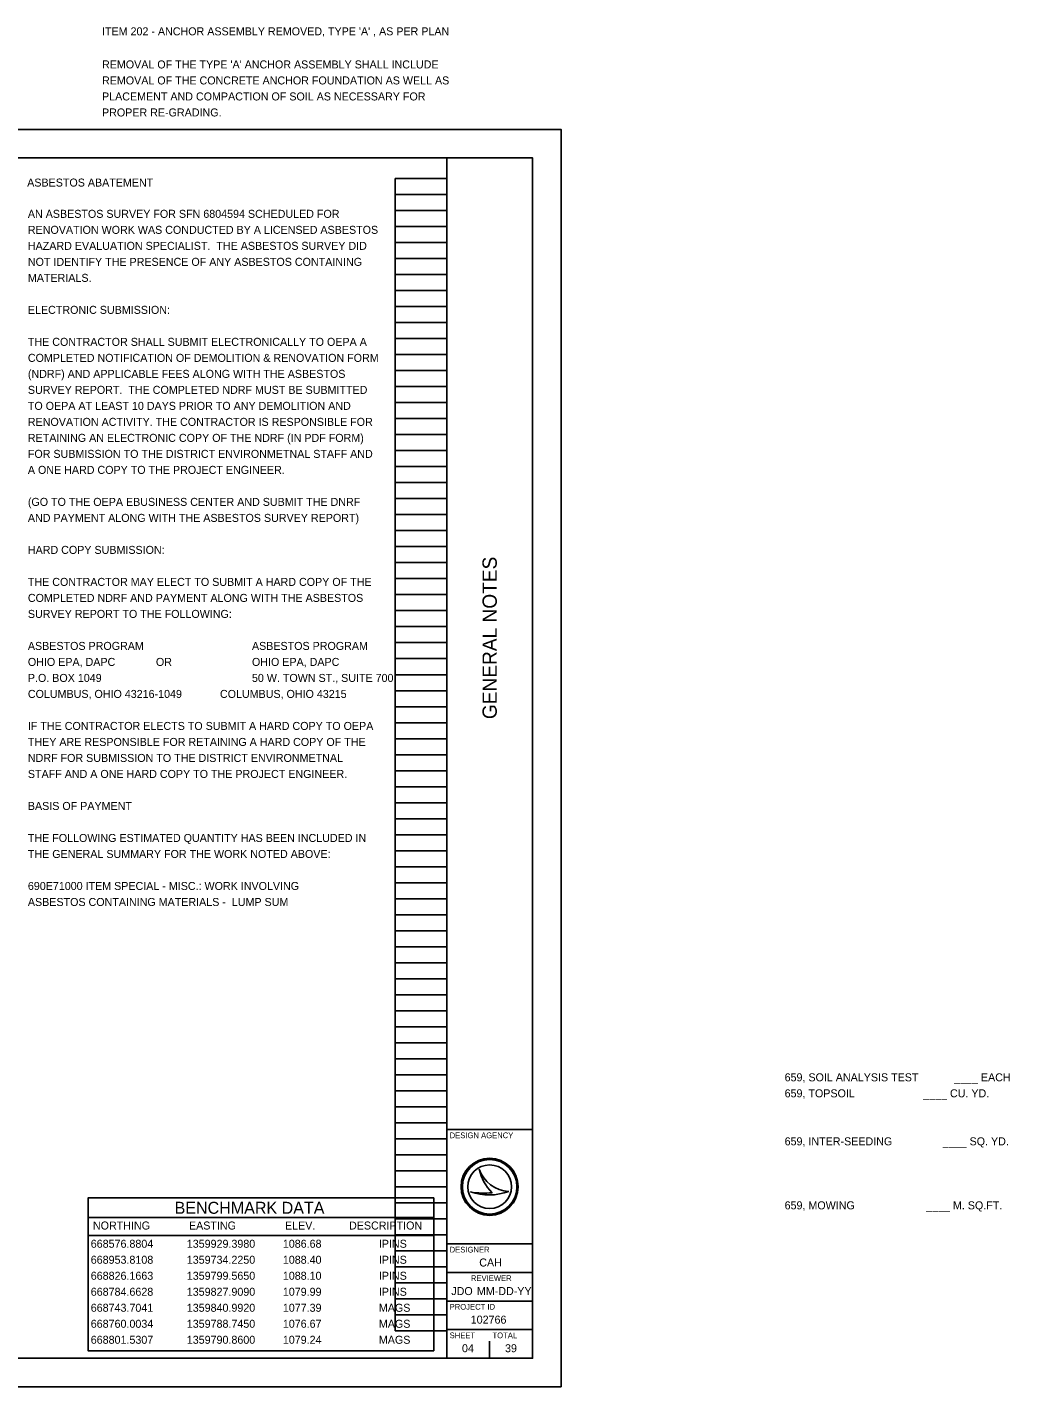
# Model space of a CAD drawing. Extents: x 0 to 41.8, y 0 to 23.8.
# Drawn here: x 24.66 to 41.85, y 0 to 23.79 of the extents above; entities that cross this region are included whole.
import ezdxf

# ---------------------------------------------------------------- set-up
doc = ezdxf.new("R2010")
doc.units = 0
for name, color, linetype in [('Default', 7, 'Continuous'), ('SH_Border', 7, 'Continuous'), ('SH_Cut_Line', 7, 'Continuous'), ('SH_Data', 7, 'Continuous'), ('SH_Text', 7, 'Continuous')]:
    doc.layers.add(name, color=color, linetype=linetype)

msp = doc.modelspace()

# ---------------------------------------------------------------- linework, layer by layer
at = {"layer": 'SH_Border'}
for p, q in [((32, 0.5), (32, 21.5)), ((32, 4.5), (33.5, 4.5)), ((32, 2.5), (33.5, 2.5)), ((32, 2), (33.5, 2)), ((32, 1.5), (33.5, 1.5)), ((32, 1), (33.5, 1))]:
    msp.add_line(p, q, dxfattribs=at)
msp.add_lwpolyline([(1.5, 21.5), (33.5, 21.5), (33.5, 0.5), (1.5, 0.5)], close=True, dxfattribs=at)
at = {"layer": 'SH_Cut_Line'}
msp.add_lwpolyline([(0, 0), (34, 0), (34, 22), (0, 22)], close=True, dxfattribs=at)
at = {"layer": 'SH_Data'}
for p, q in [((31.1, 0.98), (31.1, 21.14)), ((31.1, 21.14), (32, 21.14)), ((32, 0.98), (32, 21.14)), ((31.1, 20.86), (32, 20.86)), ((31.1, 20.58), (32, 20.58)), ((31.1, 20.3), (32, 20.3)), ((31.1, 20.02), (32, 20.02)), ((31.1, 19.74), (32, 19.74)), ((31.1, 19.46), (32, 19.46)), ((31.1, 19.18), (32, 19.18)), ((31.1, 18.9), (32, 18.9)), ((31.1, 18.62), (32, 18.62)), ((31.1, 18.34), (32, 18.34)), ((31.1, 18.06), (32, 18.06)), ((31.1, 17.78), (32, 17.78)), ((31.1, 17.5), (32, 17.5)), ((31.1, 17.22), (32, 17.22)), ((31.1, 16.94), (32, 16.94)), ((31.1, 16.66), (32, 16.66)), ((31.1, 16.38), (32, 16.38)), ((31.1, 16.1), (32, 16.1)), ((31.1, 15.82), (32, 15.82)), ((31.1, 15.54), (32, 15.54)), ((31.1, 15.26), (32, 15.26)), ((31.1, 14.98), (32, 14.98)), ((31.1, 14.7), (32, 14.7)), ((31.1, 14.42), (32, 14.42)), ((31.1, 14.14), (32, 14.14)), ((31.1, 13.86), (32, 13.86)), ((31.1, 13.58), (32, 13.58)), ((31.1, 13.3), (32, 13.3)), ((31.1, 13.02), (32, 13.02)), ((31.1, 12.74), (32, 12.74)), ((31.1, 12.46), (32, 12.46)), ((31.1, 12.18), (32, 12.18)), ((31.1, 11.9), (32, 11.9)), ((31.1, 11.62), (32, 11.62)), ((31.1, 11.34), (32, 11.34)), ((31.1, 11.06), (32, 11.06)), ((31.1, 10.78), (32, 10.78)), ((31.1, 10.5), (32, 10.5)), ((31.1, 10.22), (32, 10.22)), ((31.1, 9.94), (32, 9.94)), ((31.1, 9.66), (32, 9.66)), ((31.1, 9.38), (32, 9.38)), ((31.1, 9.1), (32, 9.1)), ((31.1, 8.82), (32, 8.82)), ((31.1, 8.54), (32, 8.54)), ((31.1, 8.26), (32, 8.26)), ((31.1, 7.98), (32, 7.98)), ((31.1, 7.7), (32, 7.7)), ((31.1, 7.42), (32, 7.42)), ((31.1, 7.14), (32, 7.14)), ((31.1, 6.86), (32, 6.86)), ((31.1, 6.58), (32, 6.58)), ((31.1, 6.3), (32, 6.3)), ((31.1, 6.02), (32, 6.02)), ((31.1, 5.74), (32, 5.74)), ((31.1, 5.46), (32, 5.46)), ((31.1, 5.18), (32, 5.18)), ((31.1, 4.9), (32, 4.9)), ((31.1, 4.62), (32, 4.62)), ((31.1, 4.34), (32, 4.34)), ((31.1, 4.06), (32, 4.06)), ((32.567, 3.81), (32.567, 3.81)), ((31.1, 3.78), (32, 3.78)), ((31.1, 3.5), (32, 3.5)), ((32.417, 3.41), (32.417, 3.41)), ((32.75, 3.5), (32.75, 3.5)), ((33.087, 3.419), (33.087, 3.419)), ((31.1, 3.22), (32, 3.22)), ((31.1, 2.94), (32, 2.94)), ((31.1, 2.66), (32, 2.66)), ((31.1, 2.38), (32, 2.38)), ((31.1, 2.1), (32, 2.1)), ((31.1, 1.82), (32, 1.82)), ((31.1, 1.54), (32, 1.54)), ((31.1, 1.26), (32, 1.26)), ((31.1, 0.98), (32, 0.98)), ((32.75, 0.5), (32.75, 0.8)), ((32.375, 0.675), (32.375, 0.675))]:
    msp.add_line(p, q, dxfattribs=at)
for radius in [0.5, 0.477, 0.477, 0.382]:
    msp.add_circle((32.75, 3.5), radius, dxfattribs=at)
for centre, radius, start, end in [((33.116, 3.998), 0.58, 198.9257, 198.9319), ((33.347, 3.97), 0.796, 191.6379, 191.6421), ((33.116, 3.998), 0.58, 198.9319, 267.1657), ((33.347, 3.97), 0.796, 191.6421, 226.0947), ((32.739, 4.37), 1.013, 251.4576, 290.0832), ((32.648, 4.654), 1.266, 259.4964, 259.4995), ((32.739, 4.37), 1.013, 251.4527, 251.4576), ((32.648, 4.654), 1.266, 259.4995, 276.6672)]:
    msp.add_arc(centre, radius, start, end, dxfattribs=at)
at = {"layer": 'SH_Text'}
for points in [[(25.726, 2.962), (31.771, 2.962), (31.771, 3.305), (25.726, 3.305)], [(25.726, 2.648), (31.771, 2.648), (31.771, 2.962), (25.726, 2.962)], [(25.726, 2.648), (31.771, 2.648), (31.771, 0.631), (25.726, 0.631)]]:
    msp.add_lwpolyline(points, close=True, dxfattribs=at)

# ---------------------------------------------------------------- texts
at = {"layer": 'Default'}
for s, height, p in [('BENCHMARK DATA', 0.21, (27.239, 3.027)), ('NORTHING', 0.14, (25.81, 2.752)), ('EASTING', 0.14, (27.49, 2.752)), ('ELEV.', 0.14, (29.17, 2.752)), ('DESCRIPTION', 0.14, (30.29, 2.752)), ('668576.8804', 0.14, (25.772, 2.433)), ('1359929.3980', 0.14, (27.452, 2.433)), ('1086.68', 0.14, (29.132, 2.433)), ('IPINS', 0.14, (30.812, 2.433)), ('668953.8108', 0.14, (25.772, 2.153)), ('1359734.2250', 0.14, (27.452, 2.153)), ('1088.40', 0.14, (29.132, 2.153)), ('IPINS', 0.14, (30.812, 2.153)), ('668826.1663', 0.14, (25.772, 1.873)), ('1359799.5650', 0.14, (27.452, 1.873)), ('1088.10', 0.14, (29.132, 1.873)), ('IPINS', 0.14, (30.812, 1.873)), ('668784.6628', 0.14, (25.772, 1.593)), ('1359827.9090', 0.14, (27.452, 1.593)), ('1079.99', 0.14, (29.132, 1.593)), ('IPINS', 0.14, (30.812, 1.593)), ('668743.7041', 0.14, (25.772, 1.313)), ('1359840.9920', 0.14, (27.452, 1.313)), ('1077.39', 0.14, (29.132, 1.313)), ('MAGS', 0.14, (30.812, 1.313)), ('668760.0034', 0.14, (25.772, 1.033)), ('1359788.7450', 0.14, (27.452, 1.033)), ('1076.67', 0.14, (29.132, 1.033)), ('MAGS', 0.14, (30.812, 1.033)), ('668801.5307', 0.14, (25.772, 0.753)), ('1359790.8600', 0.14, (27.452, 0.753)), ('1079.24', 0.14, (29.132, 0.753)), ('MAGS', 0.14, (30.812, 0.753))]:
    msp.add_text(s, height=height, dxfattribs=at).set_placement(p)
at = {"layer": 'SH_Data'}
msp.add_text('GENERAL NOTES', height=0.25, rotation=90, dxfattribs=at).set_placement((32.875, 11.682))
for s, height, p in [('DESIGN AGENCY', 0.1, (32.05, 4.35)), ('DESIGNER', 0.1, (32.05, 2.35)), ('CAH', 0.14, (32.568, 2.105)), ('REVIEWER', 0.1, (32.422, 1.85)), ('JDO', 0.14, (32.079, 1.605)), ('MM-DD-YY', 0.14, (32.527, 1.605)), ('PROJECT ID', 0.1, (32.05, 1.35)), ('102766', 0.14, (32.419, 1.105)), ('SHEET', 0.1, (32.05, 0.85)), ('04', 0.14, (32.266, 0.605)), ('TOTAL', 0.1, (32.8, 0.85)), ('39', 0.14, (33.019, 0.605))]:
    msp.add_text(s, height=height, dxfattribs=at).set_placement(p)
at = {"layer": 'SH_Text'}
for s, p in [("ITEM 202 - ANCHOR ASSEMBLY REMOVED, TYPE 'A' , AS PER PLAN", (25.969, 23.646)), ("REMOVAL OF THE TYPE 'A' ANCHOR ASSEMBLY SHALL INCLUDE", (25.969, 23.067)), ('REMOVAL OF THE CONCRETE ANCHOR FOUNDATION AS WELL AS', (25.969, 22.787)), ('PLACEMENT AND COMPACTION OF SOIL AS NECESSARY FOR', (25.969, 22.507)), ('PROPER RE-GRADING.', (25.969, 22.227)), ('ASBESTOS ABATEMENT', (24.66, 21)), ('AN ASBESTOS SURVEY FOR SFN 6804594 SCHEDULED FOR ', (24.672, 20.453)), ('RENOVATION WORK WAS CONDUCTED BY A LICENSED ASBESTOS ', (24.672, 20.173)), ('HAZARD EVALUATION SPECIALIST.  THE ASBESTOS SURVEY DID ', (24.672, 19.893)), ('NOT IDENTIFY THE PRESENCE OF ANY ASBESTOS CONTAINING ', (24.672, 19.613)), ('MATERIALS.', (24.672, 19.333)), ('ELECTRONIC SUBMISSION:  ', (24.672, 18.773)), ('THE CONTRACTOR SHALL SUBMIT ELECTRONICALLY TO OEPA A ', (24.672, 18.213)), ('COMPLETED NOTIFICATION OF DEMOLITION & RENOVATION FORM ', (24.672, 17.933)), ('(NDRF) AND APPLICABLE FEES ALONG WITH THE ASBESTOS ', (24.672, 17.653)), ('SURVEY REPORT.  THE COMPLETED NDRF MUST BE SUBMITTED ', (24.672, 17.373)), ('TO OEPA AT LEAST 10 DAYS PRIOR TO ANY DEMOLITION AND ', (24.672, 17.093)), ('RENOVATION ACTIVITY. THE CONTRACTOR IS RESPONSIBLE FOR ', (24.672, 16.813)), ('RETAINING AN ELECTRONIC COPY OF THE NDRF (IN PDF FORM) ', (24.672, 16.533)), ('FOR SUBMISSION TO THE DISTRICT ENVIRONMETNAL STAFF AND ', (24.672, 16.253)), ('A ONE HARD COPY TO THE PROJECT ENGINEER.   ', (24.672, 15.973)), ('(GO TO THE OEPA EBUSINESS CENTER AND SUBMIT THE DNRF ', (24.672, 15.413)), ('AND PAYMENT ALONG WITH THE ASBESTOS SURVEY REPORT)', (24.672, 15.133)), ('HARD COPY SUBMISSION:', (24.672, 14.573)), ('THE CONTRACTOR MAY ELECT TO SUBMIT A HARD COPY OF THE ', (24.672, 14.013)), ('COMPLETED NDRF AND PAYMENT ALONG WITH THE ASBESTOS ', (24.672, 13.733)), ('SURVEY REPORT TO THE FOLLOWING:', (24.672, 13.453)), ('ASBESTOS PROGRAM', (24.672, 12.893)), ('ASBESTOS PROGRAM', (28.592, 12.893)), ('OHIO EPA, DAPC', (24.672, 12.613)), ('OR', (26.912, 12.613)), ('OHIO EPA, DAPC', (28.592, 12.613)), ('P.O. BOX 1049', (24.672, 12.333)), ('50 W. TOWN ST., SUITE 700', (28.592, 12.333)), ('COLUMBUS, OHIO 43216-1049', (24.672, 12.053)), ('COLUMBUS, OHIO 43215', (28.032, 12.053)), ('IF THE CONTRACTOR ELECTS TO SUBMIT A HARD COPY TO OEPA ', (24.672, 11.493)), ('THEY ARE RESPONSIBLE FOR RETAINING A HARD COPY OF THE ', (24.672, 11.213)), ('NDRF FOR SUBMISSION TO THE DISTRICT ENVIRONMETNAL ', (24.672, 10.933)), ('STAFF AND A ONE HARD COPY TO THE PROJECT ENGINEER.', (24.672, 10.653)), ('BASIS OF PAYMENT', (24.672, 10.093)), ('THE FOLLOWING ESTIMATED QUANTITY HAS BEEN INCLUDED IN ', (24.672, 9.533)), ('THE GENERAL SUMMARY FOR THE WORK NOTED ABOVE:', (24.672, 9.253)), ('690E71000 ITEM SPECIAL - MISC.: WORK INVOLVING ', (24.672, 8.693)), ('ASBESTOS CONTAINING MATERIALS -  LUMP SUM', (24.672, 8.413)), ('659, SOIL ANALYSIS TEST            ____ EACH', (37.91, 5.345)), ('659, TOPSOIL                       ____ CU. YD.', (37.91, 5.065)), ('659, INTER-SEEDING                 ____ SQ. YD.', (37.91, 4.225)), ('659, MOWING                        ____ M. SQ.FT.', (37.91, 3.105))]:
    msp.add_text(s, height=0.14, dxfattribs=at).set_placement(p)

doc.saveas('drawing.dxf')
